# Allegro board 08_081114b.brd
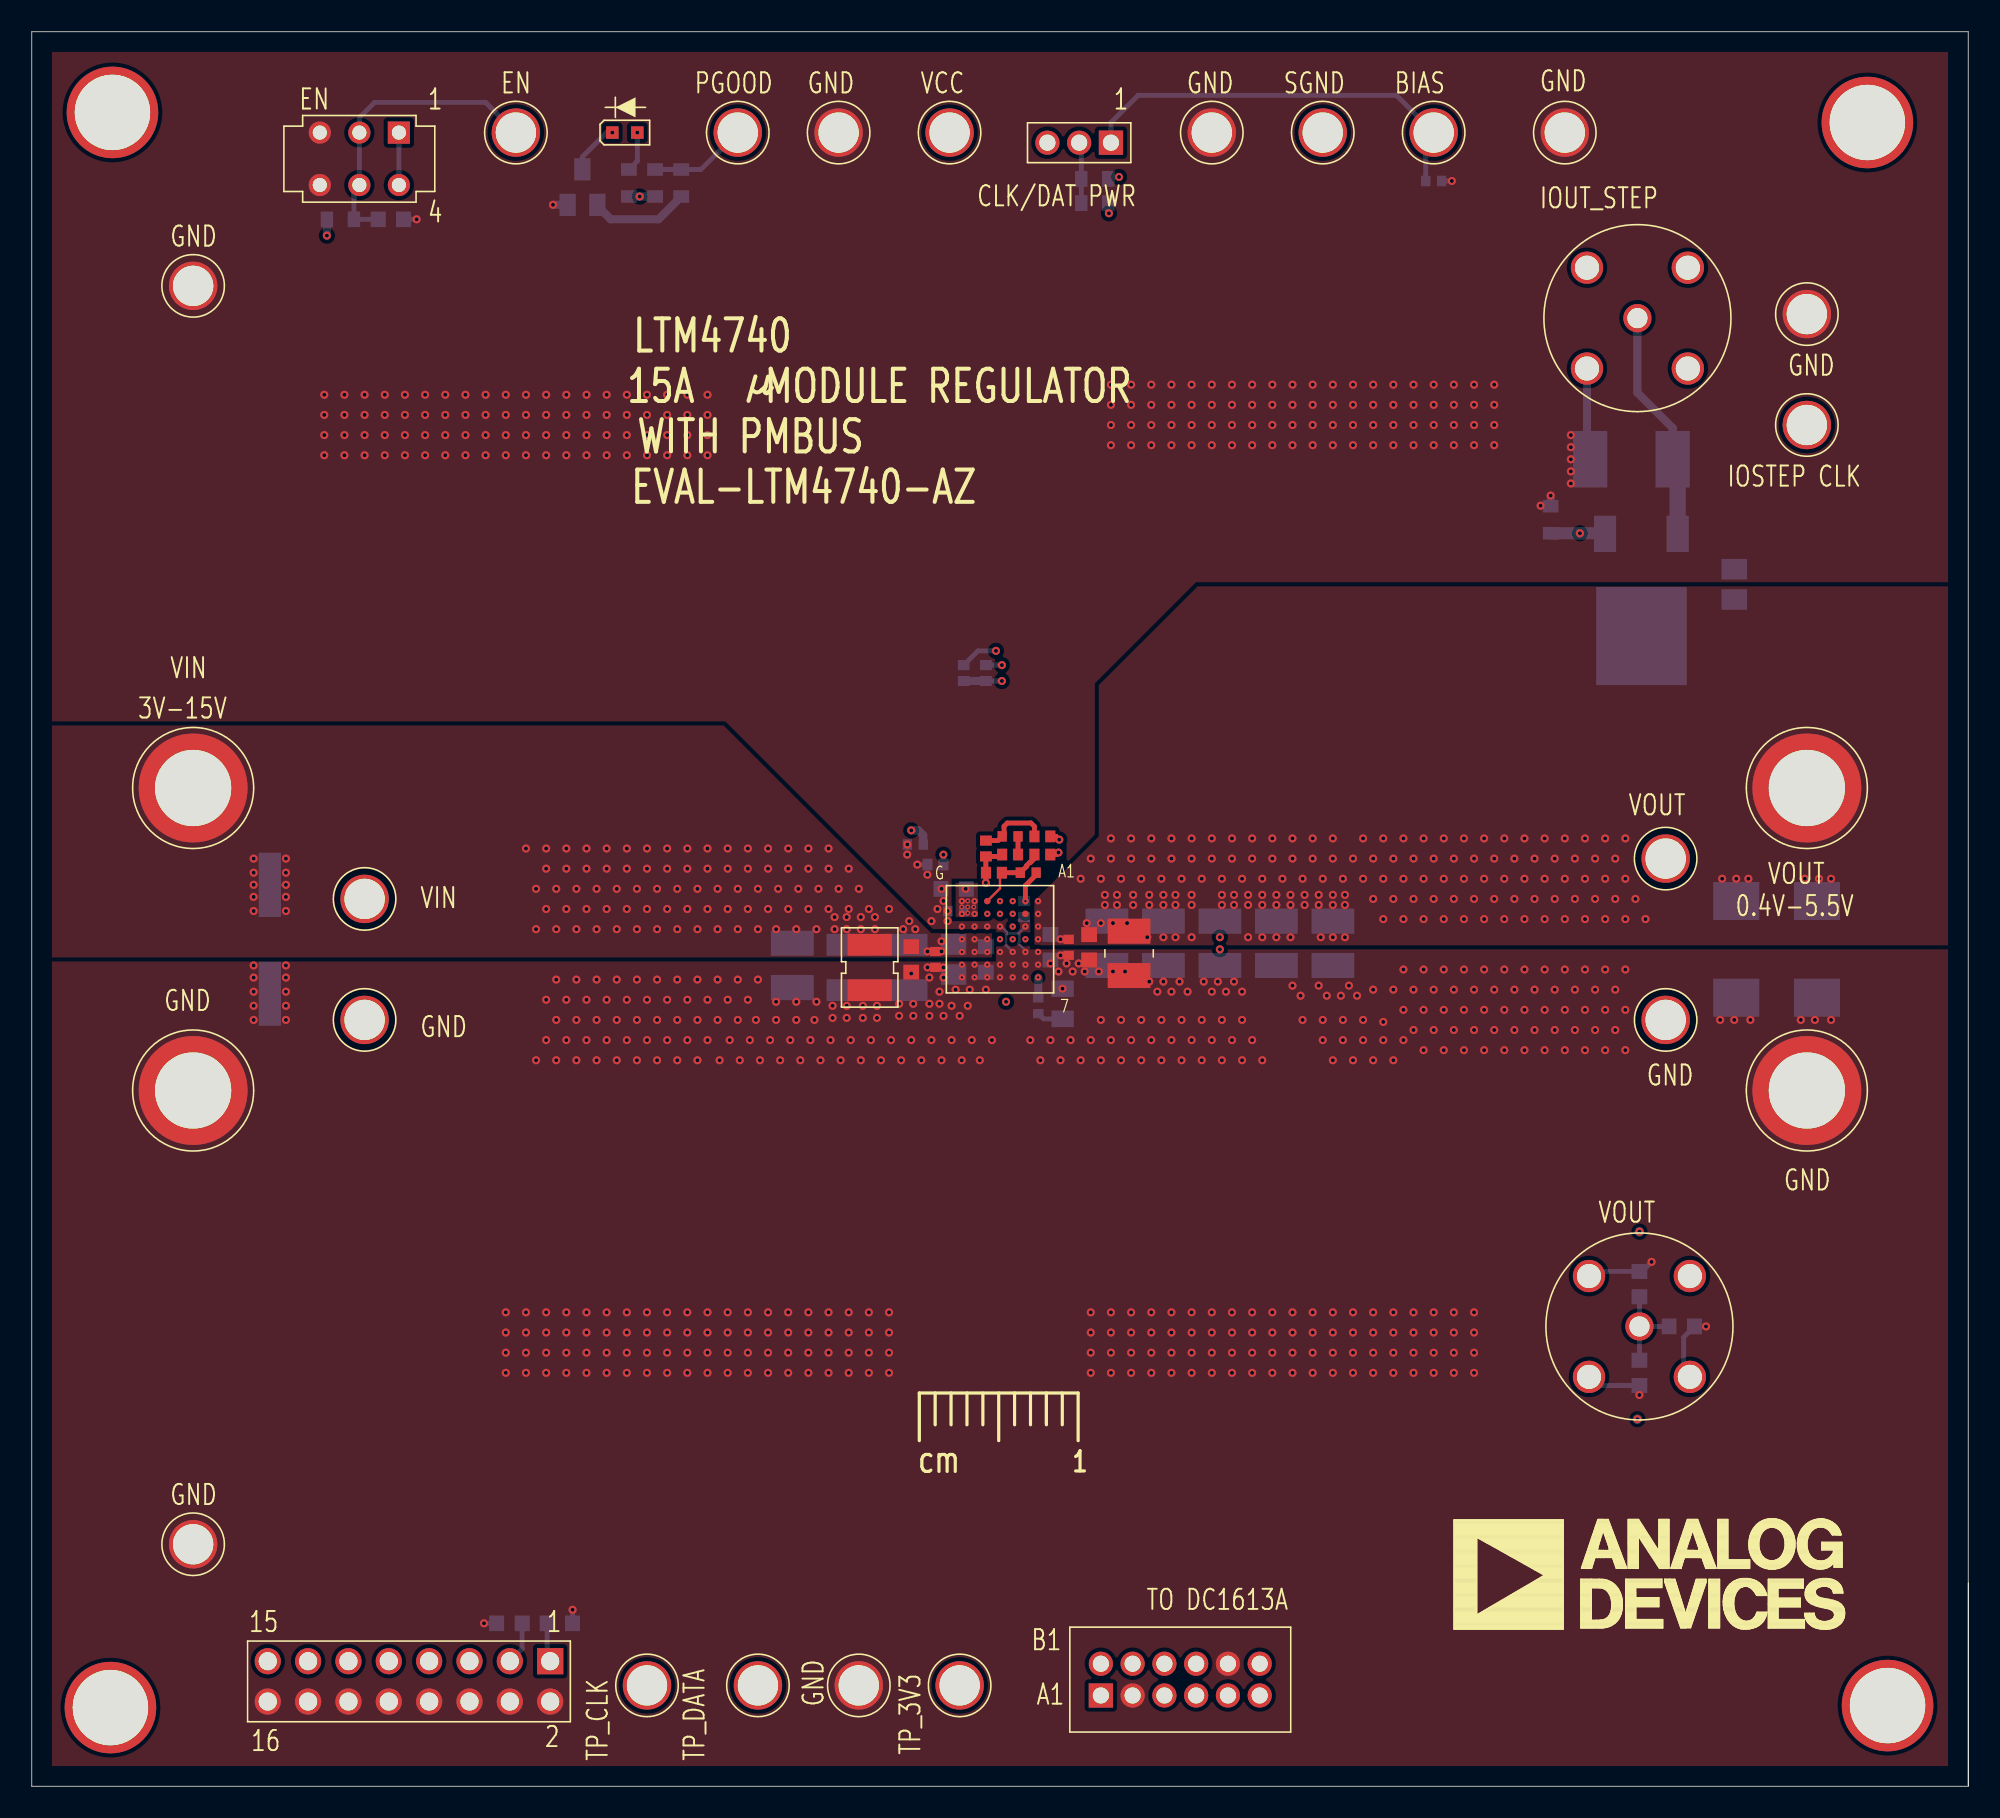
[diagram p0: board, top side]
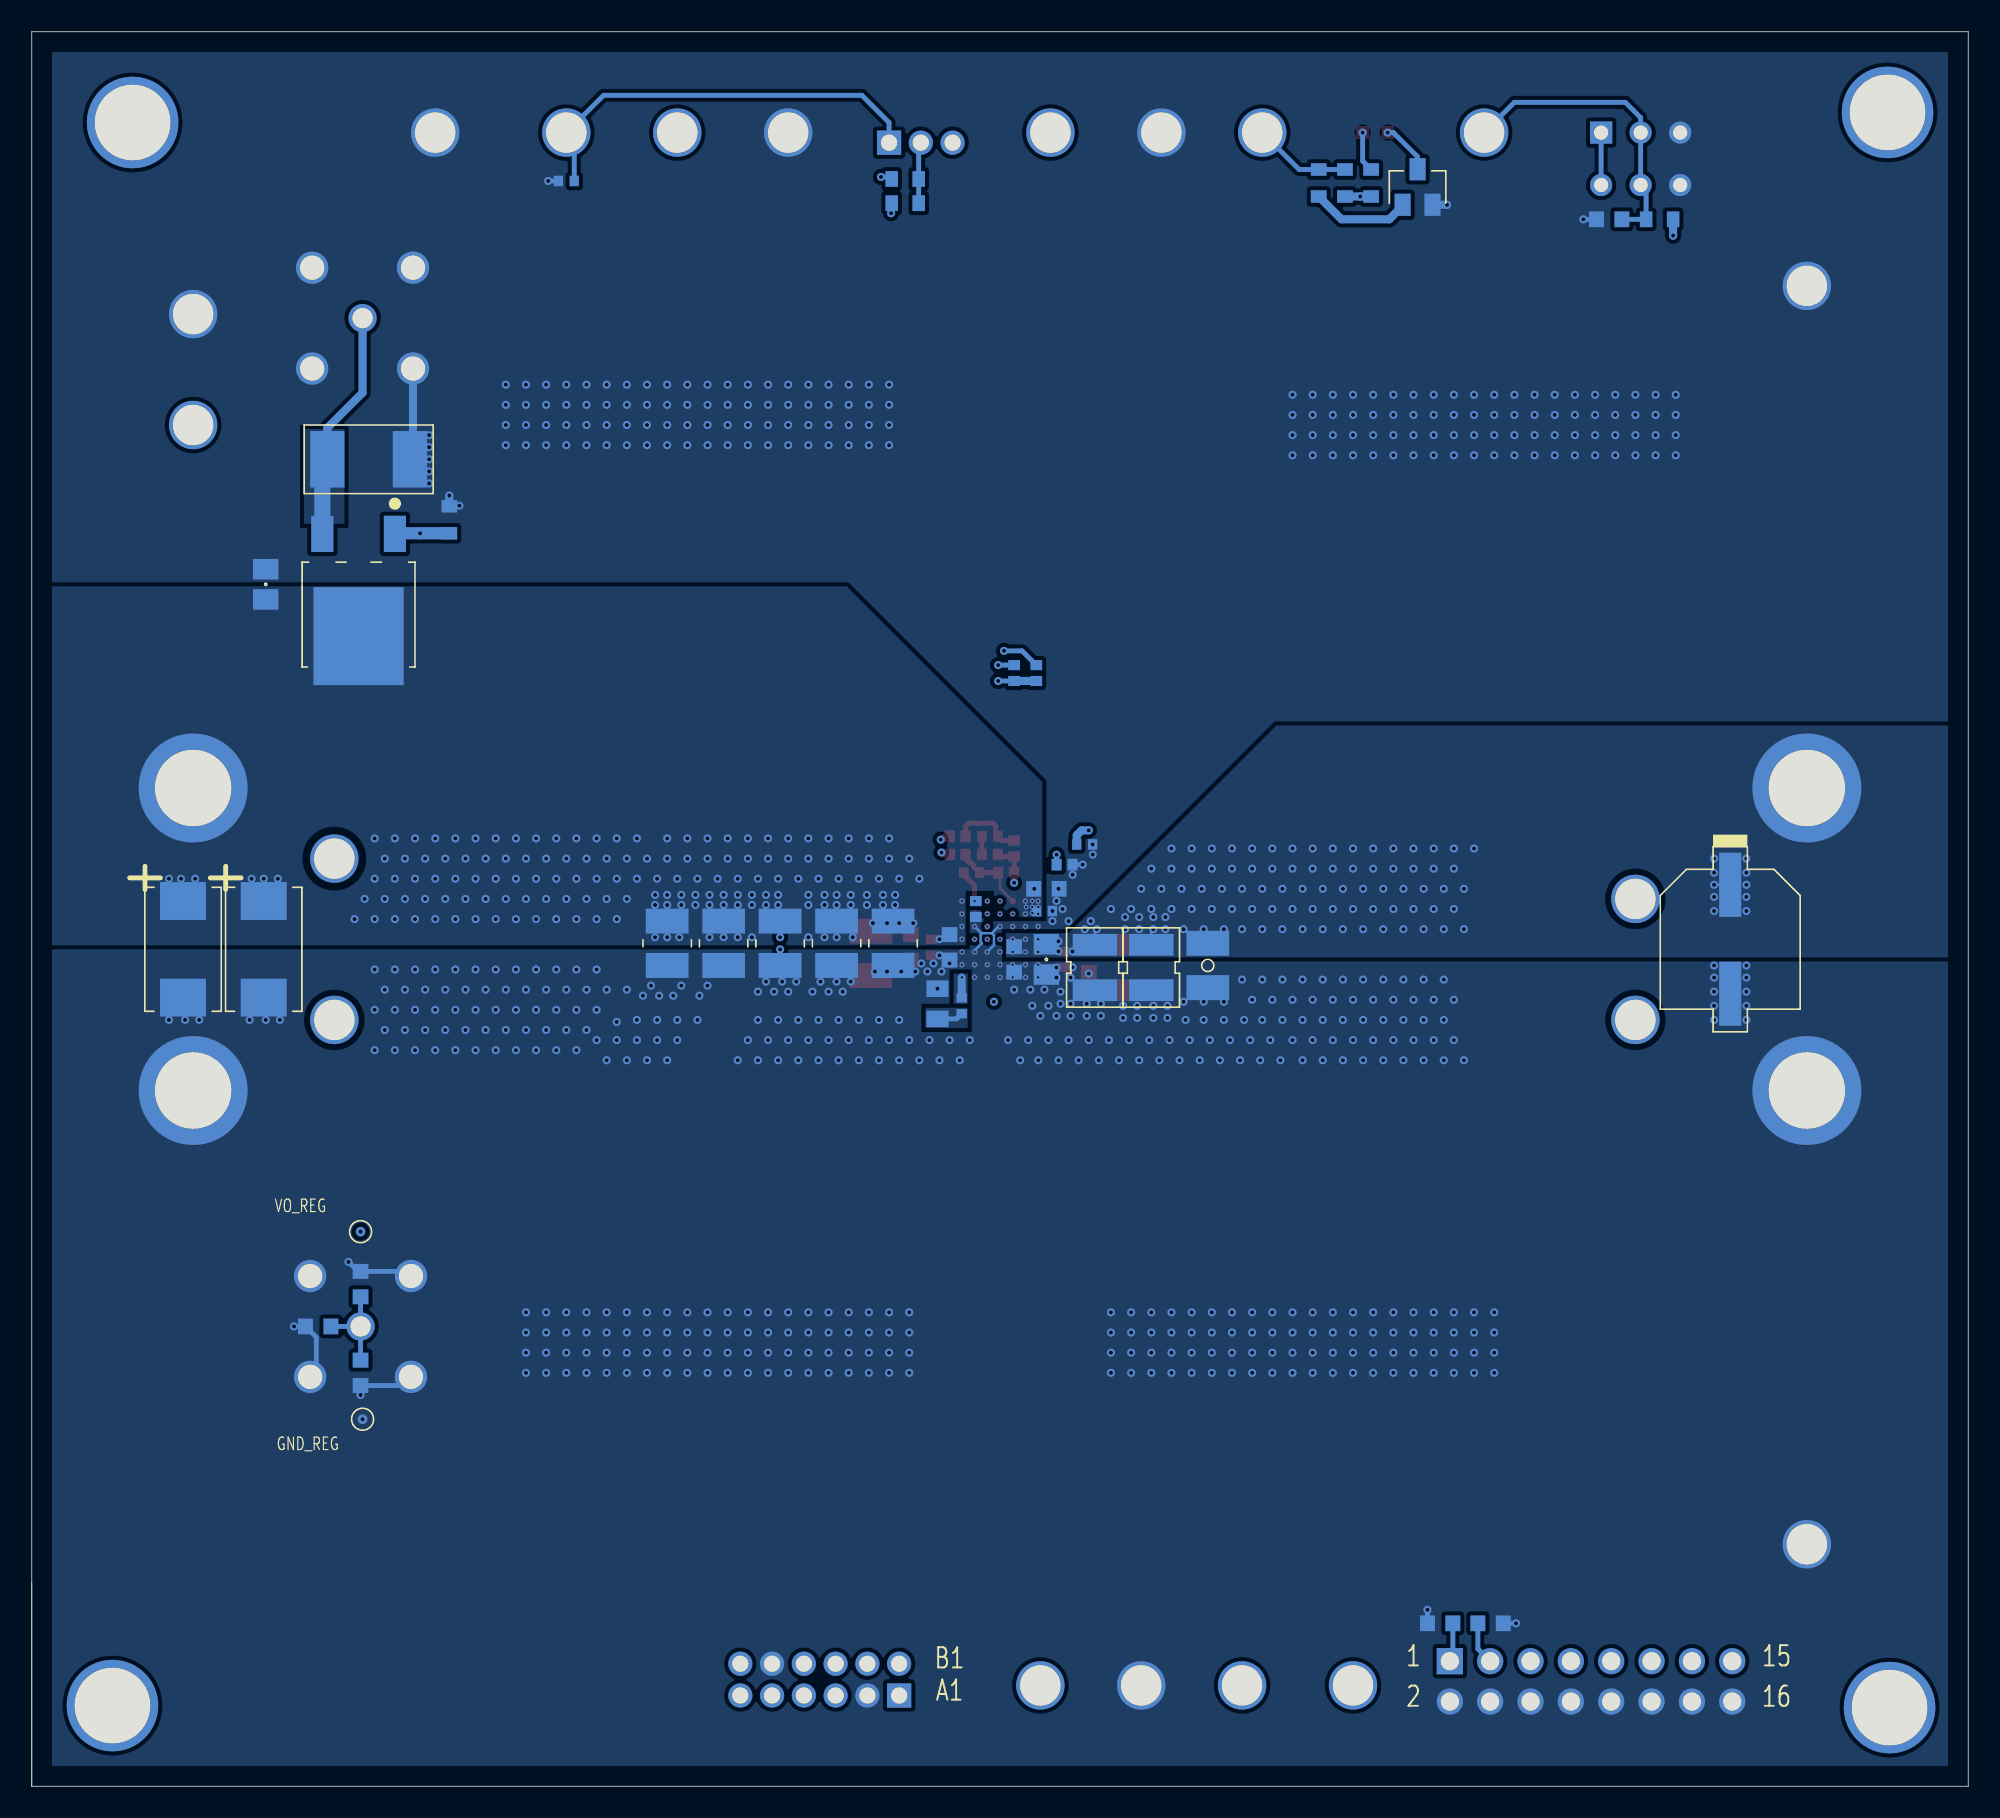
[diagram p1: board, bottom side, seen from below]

Outline 121.92 x 110.49 mm; copper layers: TOP, LAYER_2, LAYER_3, LAYER_4, LAYER_5, BOTTOM. Coordinates in mm from the lower left corner of the outline.
Outline path: 121.92,0 121.92,110.49 0,110.49 0,0 121.92,0 ; 121.92,0 121.92,12.83

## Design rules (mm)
constraint set DEFAULT: min track width 0.152

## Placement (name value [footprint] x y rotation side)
C1  1uF  [C0402]  65.28 52.83 270 top
C2  220UF  [CPLSML327W327H413]  14.99 53.34 270 bottom
C3  22UF  [C1210H110]  54.99 51.56 270 bottom
C4  22UF  [C1210H110]  51.44 51.56 270 bottom
C5  22UF  [C1210H110]  52.76 51.56 270 top
C6  TBD0402  [C0402]  63.37 49.15 270 bottom
C7  22uF  [C0805H60]  58.04 52.07 270 bottom
C8  2.2uF  [C0402]  88.27 101.09 0 bottom
C9  10uF  [C0603]  55.37 52.07 270 top
C10  1NF  [C0603]  22.61 98.68 180 bottom
C11  TBD0603  [C0603]  30.07 10.26 0 bottom
C12  0.22uF  [C0402]  56.9 52.07 270 top
C13  TBD0402  [C0402]  55.63 59.31 0 bottom
C14  TBD0603  [C0603]  33.25 10.26 180 bottom
C15  TBD0402  [C0402]  62.74 57.53 180 top
C16  TBD0402  [C0402]  61.59 59.82 180 top
C17  TBD1210  [C1210]  47.88 51.69 270 bottom
C18  2.2uF  [C0603]  66.57 52.83 270 top
C19  2.2uF  [C0603]  64.14 52.83 270 bottom
C20  10uF  [C0603]  60.07 52.07 270 bottom
C21  220uF  [C1210-2]  67.69 53.09 270 bottom
C22  220uF  [C1210-2]  69.09 52.45 270 top
C23  1uF  [C0603]  101.22 26.04 90 bottom
C24  220uF  [C1210-2]  81.91 53.09 270 bottom
C25  220uF  [C1210-2]  71.25 53.09 270 bottom
C26  1uF  [C0603]  101.22 31.62 270 bottom
C27  220uF  [C1210-2]  78.36 53.09 270 bottom
C28  1uF  [C0805H60]  107.19 75.69 90 bottom
C29  220uF  [C1210-2]  74.8 53.09 270 bottom
C30  1uF  [C0402]  58.17 55.12 180 bottom
C31  330uF  [CPLSML287W169H157]  112.4 52.71 270 bottom
C32  330uF  [CPLSML287W169H157]  107.31 52.71 270 bottom
C33  1uF  [C0603]  58.04 56.52 180 bottom
C34  1uF  [C0603]  103.89 28.96 180 bottom
J1  112404  [CNAMPHENOL112404]  101.09 92.46 0 top
J2  112404  [CNAMPHENOL112404]  101.22 28.96 0 top
NOREF  -  []  23.75 131.7 0 top
NOREF#2  -  []  77.47 146.05 0 top
NOREF#3  -  []  -223.52 -149.22 0 top
NOREF#4  -  []  89.53 3.81 0 top
NOREF#5  -  []  74.3 130.81 0 top
NOREF#6  -  []  122.56 111.12 180 top
NOREF#7  -  []  350.65 266.83 0 top
NOREF#8  -  []  -0.63 -0.63 0 top
NOREF#9  -  []  -223.52 -149.22 0 top
NOREF#10  -  [unnamed#2]  4.95 4.95 0 top
NOREF#11  -  []  0 0 90 top
NOREF#12  -  []  141.29 5.4 0 top
NOREF#13  -  [unnamed#2]  115.57 104.78 0 top
NOREF#14  -  []  -189.92 304.8 0 top
NOREF#15  -  []  -31.12 106.05 0 top
NOREF#16  -  []  157.86 321.18 0 top
NOREF#17  -  []  122.56 -0.63 90 top
NOREF#18  -  []  -0.63 111.12 270 top
NOREF#19  -  []  -31.12 80.01 0 top
NOREF#20  -  []  77.72 -27.94 0 top
NOREF#21  -  [unnamed#2]  116.84 5.08 0 top
NOREF#22  -  []  119.38 152.4 0 top
NOREF#23  -  []  -216.53 130.18 0 top
NOREF#24  -  []  61.47 16.76 0 top
NOREF#25  -  []  23.75 157.73 0 top
NOREF#26  -  [unnamed#2]  5.08 105.41 0 top
NOREF#27  -  []  -223.52 -149.22 0 top
NOREF#28  -  []  347.34 315.6 0 top
NOREF#29  -  []  -193.67 350.52 0 top
NOREF#30  -  []  0 110.49 0 top
NOREF#31  -  []  -189.97 327.66 0 top
P3  98414-G06-12ULF  [CNTHMHDR2X6L528W240H244]  67.31 5.72 0 top
P6  NCTPSMC24_NPM  [TPSMC24_NPM]  101.22 34.93 180 bottom
P10  NRPN031PAEN-RC  [CNTHMHDR1X3L326W79H235]  67.95 103.5 180 top
P11  TSW-108-07-G-D  [CNSAMTECTSW-108-08-G-D-ST]  32.64 7.87 180 top
P12  NCTPSMC24_NPM  [TPSMC24_NPM]  101.09 23.11 180 bottom
PG  LG L29K-G2J1-24-Z  [LED0603-2]  37.34 104.14 0 top
Q1  SUD50N04-8M8P-4GE3  [TO252-3]  101.35 74.68 0 bottom
Q2  BSS138TA  [SOT23]  34.67 100.71 180 bottom
R1  0  [R0402]  63.63 58.67 0 top
R2  TBD0805  [R0805]  64.9 49.28 90 bottom
R3  0  [R0402]  62.48 55.25 90 bottom
R4  TBD0402  [R0402]  56.9 58.04 180 bottom
R6  200  [R0402]  58.67 70.1 90 bottom
R9  309  [R0402]  60.07 70.1 90 bottom
R10  TBD0402  [R0402]  61.59 58.67 0 top
R12  3.01K  [R0402]  60.07 59.06 270 top
R13  3.01K  [R0402]  60.58 57.53 0 top
R16  10  [R0402]  63.63 59.82 0 top
R17  10K  [R0603]  95.63 79.76 270 bottom
R20  0.005  [R2512H31]  100.71 83.57 180 bottom
R21  3.3K  [R0603]  66.93 101.22 0 bottom
R22  3.3K  [R0603]  66.93 99.69 0 bottom
R23  20K  [R0603]  19.43 98.68 0 bottom
R25  20K  [R0603]  39.24 100.97 90 bottom
R26  100  [R0603]  40.89 100.97 270 bottom
R27  210  [R0603]  37.59 100.97 90 bottom
S1  JS202011CQN  [SWTHL354W142H217]  23.11 104.14 180 top
TP1  2501-2-00-80-00-00-07-0  [CNMILLMAX2501]  96.52 104.14 0 top
TP2  2501-2-00-80-00-00-07-0  [CNMILLMAX2501]  57.79 104.14 0 top
TP3  2501-2-00-80-00-00-07-0  [CNMILLMAX2501]  111.76 92.71 0 top
TP4  2501-2-00-80-00-00-07-0  [CNMILLMAX2501]  88.27 104.14 0 top
TP5  2501-2-00-80-00-00-07-0  [CNMILLMAX2501]  20.95 55.88 0 top
TP6  CKFH1032-10  [CNCFCKFH1032-10]  10.16 62.87 0 top
TP7  CKFH1032-10  [CNCFCKFH1032-10]  10.16 43.82 0 top
TP8  2501-2-00-80-00-00-07-0  [CNMILLMAX2501]  20.95 48.26 0 top
TP9  2501-2-00-80-00-00-07-0  [CNMILLMAX2501]  10.16 15.24 0 top
TP10  2501-2-00-80-00-00-07-0  [CNMILLMAX2501]  74.3 104.14 0 top
TP11  2501-2-00-80-00-00-07-0  [CNMILLMAX2501]  10.16 94.49 0 top
TP12  CKFH1032-10  [CNCFCKFH1032-10]  111.76 62.87 0 top
TP13  CKFH1032-10  [CNCFCKFH1032-10]  111.76 43.82 0 top
TP14  2501-2-00-80-00-00-07-0  [CNMILLMAX2501]  30.48 104.14 90 top
TP15  2501-2-00-80-00-00-07-0  [CNMILLMAX2501]  38.73 6.35 0 top
TP16  2501-2-00-80-00-00-07-0  [CNMILLMAX2501]  45.72 6.35 0 top
TP17  2501-2-00-80-00-00-07-0  [CNMILLMAX2501]  44.45 104.14 90 top
TP18  2501-2-00-80-00-00-07-0  [CNMILLMAX2501]  58.42 6.35 0 top
TP19  2501-2-00-80-00-00-07-0  [CNMILLMAX2501]  102.87 58.42 0 top
TP20  2501-2-00-80-00-00-07-0  [CNMILLMAX2501]  102.87 48.26 0 top
TP21  2501-2-00-80-00-00-07-0  [CNMILLMAX2501]  111.76 85.72 0 top
TP22  2501-2-00-80-00-00-07-0  [CNMILLMAX2501]  81.28 104.14 0 top
TP23  2501-2-00-80-00-00-07-0  [CNMILLMAX2501]  50.8 104.14 0 top
TP24  2501-2-00-80-00-00-07-0  [CNMILLMAX2501]  52.07 6.35 0 top
U1  LTM4740EY#PBF  [BGA49_6_25X6_25_H5_39_SMD]  60.96 53.34 180 top

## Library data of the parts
C1 C30 = CAP: User Part Number: UPN; Tolerance: 10; alternate symbols: (C0402); part number: CAP_SM-1UF,10V,10,E017585,C0402; tolerance: 10
C2 = CAPP: Tolerance: 20; User Part Number: UPN; alternate symbols: (CPLSML327W327H413); part number: CAPP_SM-220UF,25V,20,E064730,CPLSML327W327H413; tolerance: 20
C3-C5 = CAP: Tolerance: 10; User Part Number: UPN; alternate symbols: (C1210H110); part number: CAP_SM-22UF,25V,10,E063473,C1210H110; tolerance: 10
C6 C13 C15 C16 = CAP: User Part Number: UPN; alternate symbols: (C0402); part number: CAP_SM-TBD0402,TBD0402,TBD0402,E000381,C0402
C7 = CAP: Tolerance: 20; User Part Number: UPN; alternate symbols: (C0805H60); part number: CAP_SM-22UF,25V,20,E032575,C0805H60; tolerance: 20
C8 = CAP: User Part Number: UPN; Tolerance: 20; alternate symbols: (C0402); part number: CAP_SM-2.2UF,6.3V,20,E007139,C0402; tolerance: 20
C9 C20 = CAP: User Part Number: UPN; Tolerance: 20; alternate symbols: (C0603); part number: CAP_SM-10UF,25V,20,E023693,C0603; tolerance: 20
C10 = CAP: User Part Number: UPN; Tolerance: 10; alternate symbols: (C0603); part number: CAP_SM-1NF,100V,10,E042847,C0603; tolerance: 10
C11 C14 = CAP: User Part Number: UPN; alternate symbols: (C0603); part number: CAP_SM-TBD0603,TBD0603,TBD0603,E000382,C0603
C12 = CAP: User Part Number: UPN; Tolerance: 10; alternate symbols: (C0402); part number: CAP_SM-0.22UF,25V,10,E034257,C0402; tolerance: 10
C17 = CAP: User Part Number: UPN; alternate symbols: (C1210); part number: CAP_SM-TBD1210,TBD1210,TBD1210,E016202,C1210
C18 C19 = CAP: User Part Number: UPN; Tolerance: 10; alternate symbols: (C0603); part number: CAP_SM-2.2UF,10V,10,E015288,C0603; tolerance: 10
C21 C22 C24 C25 C27 C29 = CAP: Tolerance: 20; User Part Number: UPN; alternate symbols: (C1210-2); part number: CAP_SM-220UF,6.3V,20,E031200,C1210-2; tolerance: 20
C23 C26 C33 C34 = CAP: User Part Number: UPN; Tolerance: 10; alternate symbols: (C0603); part number: CAP_SM-1UF,25V,10,E026591,C0603; tolerance: 10
C28 = CAP: Tolerance: 10; User Part Number: UPN; alternate symbols: (C0805H60); part number: CAP_SM-1UF,25V,10,E007664,C0805H60; tolerance: 10
C31 C32 = CAPP: Tolerance: 20; User Part Number: UPN; alternate symbols: (CPLSML287W169H157); part number: CAPP_SM-330UF,10V,20,E013491,CPLSML287W169H157; tolerance: 20
J1 J2 = CNBNC5P: Tolerance: N/A; User Part Number: UPN; alternate symbols: (CNAMPHENOL112404); part number: CNBNC5P_TH-112404,E020078,CNAMPHENOL112404; tolerance: N/A
P3 = CN12P_AB_V2: Tolerance: N/A; User Part Number: UPN; alternate symbols: (CNTHMHDR2X6L528W240H244); part number: CN12P_AB_V2_TH-98414-G06-12ULF,E032251,CNTHMHDR2X6L528W240H244; tolerance: N/A
P6 P12 = NC1P: Tolerance: N/A; User Part Number: UPN; alternate symbols: (TPSMC24_NPM); part number: NC1P_SM-NCTPSMC24_NPM,E056623,TPSMC24_NPM; tolerance: N/A
P10 = CN3P: Tolerance: N/A; User Part Number: UPN; alternate symbols: (CNTHMHDR1X3L326W79H235); part number: CN3P_TH-NRPN031PAEN-RC,E048452,CNTHMHDR1X3L326W79H235; tolerance: N/A
P11 = CN16P_ODD_EVEN: Tolerance: N/A; User Part Number: UPN; alternate symbols: (CNSAMTECTSW-108-08-G-D-ST); part number: CN16P_ODD_EVEN_TH-TSW-108-07-G-D,E007878,CNSAMTECTSW-108-08-G-D-ST; tolerance: N/A
PG = DIOLED: Tolerance: N/A; User Part Number: UPN; alternate symbols: (LED0603-2); part number: DIOLED_SM-LG L29K-G2J1-24-Z,N/A,N/A,E010948,LED0603-2; tolerance: N/A
Q1 = TRANNMOSFET_V8: Tolerance: N/A; User Part Number: UPN; alternate symbols: (TO252-3); part number: TRANNMOSFET_V8_SM-SUD50N04-8M8P-4GE3,E027839,TO252-3; tolerance: N/A
Q2 = TRANBSS138: User Part Number: UPN; Tolerance: N/A; alternate symbols: (SOT23); part number: TRANBSS138_SM-BSS138-7-F,E004635,SOT23; tolerance: N/A
R1 R3 = RES: User Part Number: UPN; Tolerance: JUMPER; alternate symbols: (R0402); part number: RES_SM-0,E003438,1/10W,JUMPER,R0402; tolerance: JUMPER
R2 = RES: User Part Number: UPN; alternate symbols: (R0805); part number: RES_SM-TBD0805,E004051,TBD0805,TBD0805,R0805
R4 R10 = RES: User Part Number: UPN; alternate symbols: (R0402); part number: RES_SM-TBD0402,E004049,TBD0402,TBD0402,R0402
R6 = RES: User Part Number: UPN; Tolerance: 1; alternate symbols: (R0402); part number: RES_SM-200,E003753,1/10W,1,R0402; tolerance: 1
R9 = RES: User Part Number: UPN; Tolerance: 1; alternate symbols: (R0402); part number: RES_SM-309,E006547,1/10W,1,R0402; tolerance: 1
R12 R13 = RES: User Part Number: UPN; Tolerance: 1; alternate symbols: (R0402); part number: RES_SM-3.01K,E027299,1/10W,1,R0402; tolerance: 1
R16 = RES: User Part Number: UPN; Tolerance: 1; alternate symbols: (R0402); part number: RES_SM-10,E003768,1/10W,1,R0402; tolerance: 1
R17 = RES: User Part Number: UPN; Tolerance: 1; alternate symbols: (R0603); part number: RES_SM-10K,E003671,1/10W,1,R0603; tolerance: 1
R20 = RES: User Part Number: UPN; Tolerance: 1; alternate symbols: (R2512H31); part number: RES_SM-0.005,E035239,1W,1,R2512H31; tolerance: 1
R21 R22 = RES: User Part Number: UPN; Tolerance: 5; alternate symbols: (R0603); part number: RES_SM-3.3K,E036086,1/4W,5,R0603; tolerance: 5
R23 = RES: User Part Number: UPN; Tolerance: 5; alternate symbols: (R0603); part number: RES_SM-20K,E003851,1/10W,5,R0603; tolerance: 5
R25 = RES: User Part Number: UPN; Tolerance: 5; alternate symbols: (R0603); part number: RES_SM-20K,E060185,1/10W,5,R0603; tolerance: 5
R26 = RES: User Part Number: UPN; Tolerance: 1; alternate symbols: (R0603); part number: RES_SM-100,E003668,1/10W,1,R0603; tolerance: 1
R27 = RES: User Part Number: UPN; Tolerance: 1; alternate symbols: (R0603); part number: RES_SM-210,E042869,1/10W,1,R0603; tolerance: 1
S1 = SWDPDT_V5: Tolerance: N/A; User Part Number: UPN; alternate symbols: (SWTHL354W142H217); part number: SWDPDT_V5_TH-JS202011CQN,E025828,SWTHL354W142H217; tolerance: N/A
TP1-TP5 TP8-TP11 TP14-TP24 = CNTP1P: User Part Number: UPN; Tolerance: N/A; alternate symbols: (CNMILLMAX2501); part number: CNTP1P_TH-2501-2-00-80-00-00-07-0,E031108,CNMILLMAX2501; tolerance: N/A
TP6 TP7 TP12 TP13 = CNTP1P: Tolerance: N/A; User Part Number: UPN; alternate symbols: (CNCFCKFH1032-10); part number: CNTP1P_TH-CKFH1032-10,E050511,CNCFCKFH1032-10; tolerance: N/A
U1 = ADLTM4740: Tolerance: N/A; User Part Number: UPN; alternate symbols: (BGA49_6_25X6_25_H5_39_SMD); part number: ADLTM4740_SM-LTM4740EY#PBF,E064685,BGA49_6_25X6_25_H5_39_SMD; tolerance: N/A

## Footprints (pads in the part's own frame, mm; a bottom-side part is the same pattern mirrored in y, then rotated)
BGA49_6_25X6_25_H5_39_SMD
  round 0.406 smd: A1(-2.4,-2.4) A2(-2.4,-1.6) A3(-2.4,-0.8) A4(-2.4,0) A5(-2.4,0.8) A6(-2.4,1.6) A7(-2.4,2.4) B1(-1.6,-2.4) B2(-1.6,-1.6) B3(-1.6,-0.8) B4(-1.6,0) B5(-1.6,0.8) B6(-1.6,1.6) B7(-1.6,2.4) C1(-0.8,-2.4) C2(-0.8,-1.6) C3(-0.8,-0.8) C4(-0.8,0) C5(-0.8,0.8) C6(-0.8,1.6) C7(-0.8,2.4) D1(0,-2.4) D2(0,-1.6) D3(0,-0.8) D4(0,0) D5(0,0.8) D6(0,1.6) D7(0,2.4) E1(0.8,-2.4) E2(0.8,-1.6) E3(0.8,-0.8) E4(0.8,0) E5(0.8,0.8) E6(0.8,1.6) E7(0.8,2.4) F1(1.6,-2.4) F2(1.6,-1.6) F3(1.6,-0.8) F4(1.6,0) F5(1.6,0.8) F6(1.6,1.6) F7(1.6,2.4) G1(2.4,-2.4) G2(2.4,-1.6) G3(2.4,-0.8) G4(2.4,0) G5(2.4,0.8) G6(2.4,1.6) G7(2.4,2.4)
C0402
  rect 0.584x0.66 smd: 1(-0.5,0) 2(0.5,0)
C0603
  rect 0.94x0.991 smd: 1(-0.8,0) 2(0.8,0)
C0805H60
  rect 1.295x1.6 smd: 1(-0.953,0) 2(0.953,0)
C1210
  rect 1.575x2.692 smd: 1(-1.397,0) 2(1.397,0)
C1210-2
  rect 1.575x2.692 smd: 1(-1.397,0) 2(1.397,0)
C1210H110
  rect 1.372x2.794 smd: 1(-1.431,0) 2(1.431,0)
CNAMPHENOL112404
  round 1.778 hole 1.27: 1(0,0)
  round 2.032 hole 1.524: 2(-3.175,3.175) 3(3.175,3.175) 4(3.175,-3.175) 5(-3.175,-3.175)
CNCFCKFH1032-10
  round 6.858 hole 4.801: 1(0,0)
CNMILLMAX2501
  round 3.048 hole 2.54: 1(0,0)
CNSAMTECTSW-108-08-G-D-ST
  rect 1.651x1.651 hole 1.143: 1(0,0)
  round 1.651 hole 1.143: 2(0,2.54) 3(2.54,0) 4(2.54,2.54) 5(5.08,0) 6(5.08,2.54) 7(7.62,0) 8(7.62,2.54) 9(10.16,0) 10(10.16,2.54) 11(12.7,0) 12(12.7,2.54) 13(15.24,0) 14(15.24,2.54) 15(17.78,0) 16(17.78,2.54)
CNTHMHDR1X3L326W79H235
  rect 1.524x1.524 hole 1.016: 1(0,0)
  round 1.524 hole 1.016: 2(2,0) 3(4,0)
CNTHMHDR2X6L528W240H244
  rect 1.524x1.524 hole 1.016: A1(0,0)
  round 1.524 hole 1.016: A2(2,0) A3(4,0) A4(6,0) A5(8,0) A6(10,0) B1(0,2) B2(2,2) B3(4,2) B4(6,2) B5(8,2) B6(10,2)
CPLSML287W169H157
  rect 2.388x2.896 smd: N(3.044,0) P(-3.044,0)
CPLSML327W327H413
  rect 4.039x1.397 smd: N(3.43,0) P(-3.43,0)
LED0603-2
  rect 0.787x0.787 smd: A(0.787,0) C(-0.787,0)
R0402
  rect 0.635x0.737 smd: 1(-0.5,0) 2(0.5,0)
R0603
  rect 0.787x0.991 smd: 1(-0.85,0) 2(0.85,0)
R0805
  rect 1.041x1.397 smd: 1(-0.95,0) 2(0.95,0)
R2512H31
  rect 2.159x3.556 smd: 1(-2.6,0) 2(2.6,0)
SOT23
  rect 1.016x1.397 smd: 1(-0.94,-1.118) 2(0.94,-1.118) 3(0,1.118)
SWTHL354W142H217
  rect 1.397x1.397 hole 0.889: 1(0,0)
  round 1.397 hole 0.889: 2(2.489,0) 3(4.978,0) 4(0,3.302) 5(2.489,3.302) 6(4.978,3.302)
TO252-3
  rect 1.397x2.286 smd: 1(-2.29,-4.191) 2(2.28,-4.191)
  rect 5.69x6.172 smd: 3(0,2.248)
TPSMC24_NPM
  round 0.61 smd: 1(0,0)
unnamed#2
  round 5.766 hole 4.75 unplated: (0,0)

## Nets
3V3: P3.A3 TP18.1(N1)
AVDD: U1.B2
GND_POWER: C1.2(N2) C2.N(N2) C3.2(N2) C4.2(N2) C5.2(N2) C7.2(N2) C8.2(N2) C9.2(N2) C10.1 C11.1 C12.2(N2) C13.1 C14.1 C17.2(N2) C18.2(N2) C19.2(N2) C20.2(N2) C21.2(N2) C22.2(N2) C23.1 C24.2(N2) C25.2(N2) C26.1 C27.2(N2) C28.2(N2) C29.2(N2) C30.2(N2) C31.N(N2) C32.N(N2) C33.2(N2) C34.1 J1.2 J1.3 J1.4 J1.5(SH4) J2.2 J2.3 J2.4 J2.5(SH4) P3.A2 P3.B5 P11.2 P11.4 P11.6 P11.8 P11.10 P11.12 P11.14 P11.16(N8) P12.1(N1) Q2.2(S) R1.2(N2) R2.2(N2) R3.1 R4.2(N2) R17.1 R20.2(N2) S1.3 S1.6(NO2) TP1.1(N1) TP3.1(N1) TP7.1(N1) TP8.1(N1) TP9.1(N1) TP10.1(N1) TP11.1(N1) TP13.1(N1) TP20.1(N1) TP23.1(N1) TP24.1(N1) U1.A5 U1.A6 U1.B3 U1.B5 U1.B6 U1.B7 U1.C5 U1.C6 U1.C7 U1.D3 U1.D5 U1.D6 U1.D7 U1.E3 U1.E6 U1.E7 U1.F3 U1.F6 U1.F7 U1.G3 U1.G6 U1.G7
GND_SIGNAL: C15.1 R3.2(N2) R4.1 R6.1 R9.1 TP22.1(N1) U1.B1
VCC: C13.2(N2) P10.3(N3) R23.1 R25.1 R27.1 TP2.1(N1) U1.C2
VIN: C2.P C3.1 C4.1 C5.1 C7.1 C9.1 C12.1 C17.1 C20.1 TP5.1(N1) TP6.1(N1) U1.E4 U1.E5 U1.F4 U1.F5 U1.G4 U1.G5
BIAS: C8.1 P10.1 TP4.1(N1) U1.B4
CLK: C14.2(N2) P3.B2 P11.1 R21.2(N2) TP15.1(N1) U1.D2
DATA: C11.2(N2) P3.B1 P11.3 R22.2(N2) TP16.1(N1) U1.D1
EN: C10.2(N2) R23.2(N2) S1.2 S1.5 TP14.1(N1) U1.C4
PGOOD: R25.2(N2) R26.1 TP17.1(N1) U1.D4
UNNAMED_2_ADLTM4740_I1_PGM0: R6.2(N2) U1.C1
UNNAMED_2_ADLTM4740_I1_PGM1: R9.2(N2) U1.C3
UNNAMED_2_ADLTM4740_I1_SNSN: C15.2(N2) R1.1 R13.2(N2) U1.E1
UNNAMED_2_ADLTM4740_I1_SNSP: R10.1 R12.2(N2) R13.1 U1.E2
UNNAMED_2_ADLTM4740_I1_SW: C6.1 U1.A7
UNNAMED_2_CAP_I18_N1: C16.1 R10.2(N2)
UNNAMED_2_CAP_I18_N2: C16.2(N2) R12.1 R16.1
UNNAMED_2_CAP_I228_N2: C6.2(N2) R2.1
UNNAMED_2_CNBNC5P_I173_CNTR: J1.1 Q1.2(S) R20.1
UNNAMED_2_CNTP1P_I182_N1: Q1.1 R17.2(N2) TP21.1(N1)
UNNAMED_6_CN3P_I255_N2: P10.2 R21.1 R22.1
UNNAMED_6_DIOLED_I288_N: PG.C Q2.3
UNNAMED_6_DIOLED_I288_P: PG.A(P) R27.2(N2)
UNNAMED_6_RES_I285_N2: Q2.1 R26.2(N2)
UNNAMED_6_SWDPDTV5_I246_NC1: S1.1 S1.4
VOUT: C1.1 C18.1 C19.1 C21.1 C22.1 C23.2(N2) C24.1 C25.1 C26.2(N2) C27.1 C28.1 C29.1 C30.1 C31.P C32.P C33.1 C34.2(N2) J2.1 P6.1(N1) Q1.3 R16.2(N2) TP12.1(N1) TP19.1(N1) U1.A1 U1.A2 U1.A3 U1.A4 U1.F1 U1.F2 U1.G1 U1.G2(VOUT_8)

Pads without a net: P3 A1 A4 A5 A6 B3 B4 B6; P11 5 7 9 11 13 15

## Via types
v1: diameter 0.305, hole 0.152, TOP to BOTTOM, 52 vias
v2: diameter 0.508, hole 0.254, TOP to BOTTOM, 901 vias

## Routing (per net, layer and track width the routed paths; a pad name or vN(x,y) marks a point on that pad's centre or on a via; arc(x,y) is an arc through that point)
3V3: length 14.8
  LAYER_4 w0.305: TP18.1 59.77,6.35 62.33,3.78 69.38,3.78 P3.A3
GND_POWER: length 217.5
  TOP w0.305: v2(64.64,58.8) 64.52,58.67 R1.2
  LAYER_2 w0.152: 61.34,53.85 61.47,53.72 62.14,53.72 ; 61.34,53.85 61.05,54.14 61,54.14 ; 61.34,53.85 61.34,53.09 60.96,52.71 60.96,52.58 ; 62.48,54.1 62.48,54.06 62.14,53.72 ; 62.48,54.1 62.48,54.22 62.14,54.56 61.42,54.56 61,54.14 ; 62.48,54.1 62.6,54.1 62.99,53.71 62.98,53.7 62.98,53.1 63.36,52.72 v1(63.36,52.54) ; 62.48,54.1 62.56,54.18 ; 62.14,53.72 62.14,53.5 62.14,53.5 62.14,53.18 62.14,53.18 62.14,52.96 v1(62.56,52.54) ; 60.96,52.58 60.58,52.96 60.58,53.76 v1(60.96,54.14) 61,54.14 ; 60.96,52.58 v1(60.96,52.54)
  LAYER_3 w0.305: v2(101.09,23.11) 98.43,25.78 J2.5 98.04,27.31 77.85,47.5 77.85,50.29 75.44,52.71 v2(74.8,52.71)
  LAYER_4 w0.305: TP20.1 103,48.39 103,52.45 102.36,53.09 85.72,53.09 84.07,51.44 69.85,51.44 68.71,52.58 65.02,52.58 v2(64.77,52.32) 64.14,52.96 64.14,58.29 v2(64.64,58.8)
  LAYER_4 w0.508: J2.5 J2.4 J2.3 J2.2 ; 104.27,89.28 104.27,95.63 J1.2 J1.5
  LAYER_5 w0.152: 61.34,53.72 61.34,52.83 61.05,52.54 v1(60.96,52.54) 60.58,52.92 60.58,53.85 60.87,54.14 v1(60.96,54.14) 60.96,54.1 61.34,53.72 ; 61.34,53.72 62.14,53.72 ; 62.14,53.72 62.14,53.72 62.14,52.96 v1(62.56,52.54) 62.57,52.54 62.94,52.91 62.94,53.77 62.61,54.1 62.48,54.1 62.48,54.06 62.14,53.72
  LAYER_5 w0.305: TP8.1 24.51,51.82 56.15,51.82 v2(56.4,51.57)
  BOTTOM w0.152: R20.2 v2(96.9,83.57) ; v1(61.76,52.54) 61.34,52.96 61.34,53.59 61.47,53.72 ; 61.47,53.72 62.14,53.72 ; 61.47,53.72 61.05,54.14 v1(60.96,54.14) ; v1(62.56,52.54) 62.56,52.63 62.1,53.09 62.18,53.16 62.18,53.61 62.1,53.68 62.14,53.72 ; 62.14,53.72 v1(62.56,54.14)
  BOTTOM w0.305: C10.1 v2(24.23,98.68) ; R4.2 v2(55.75,58.04) ; C8.2 v2(89.41,101.09) ; C11.1 v2(28.47,10.26) ; J2.5 98.59,25.23 C23.1 v2(101.22,24.64) ; v2(101.98,33.02) 101.38,32.42 C26.1 98.34,32.42 J2.2 ; C14.1 v2(34.05,11.11) ; J2.4 104.01,26.17 104.01,28.28 C34.1 105.16,28.96 ; C29.2 v2(74.8,52.71)
  BOTTOM w0.508: R20.2 97.92,83.76 J1.5 ; v2(32.82,99.59) Q2.2 ; R17.1 v2(95.63,81.28)
  vias: v1(58.56,54.14) v1(58.56,51.74) v1(58.56,50.94) v1(59.36,54.14) v1(59.36,51.74) v1(59.36,50.94) v1(60.16,54.14) v1(60.16,51.74) v1(60.16,50.94) v1(60.96,51.74) v1(60.96,50.94) v1(61.76,51.74) v1(61.76,50.94) v1(62.56,51.74) v1(62.56,50.94) v1(63.36,51.74) v2(13.97,51.69) v2(13.97,50.93) v2(13.97,50.04) v2(13.97,49.15) v2(13.97,48.26) v2(16,51.69) v2(16,50.93) v2(16,50.04) v2(16,49.15) v2(16,48.26) v2(18.41,87.63) v2(18.41,86.36) v2(18.41,85.09) v2(18.41,83.82) v2(19.69,87.63) v2(19.69,86.36) v2(19.69,85.09) v2(19.69,83.82) v2(20.95,87.63) v2(20.95,86.36) v2(20.95,85.09) v2(20.95,83.82) v2(22.23,87.63) v2(22.23,86.36) v2(22.23,85.09) v2(22.23,83.82) v2(23.49,87.63) v2(23.49,86.36) v2(23.49,85.09) v2(23.49,83.82) v2(24.77,87.63) v2(24.77,86.36) v2(24.77,85.09) v2(24.77,83.82) v2(26.04,87.63) v2(26.04,86.36) v2(26.04,85.09) v2(26.04,83.82) v2(27.3,87.63) v2(27.3,86.36) v2(27.3,85.09) v2(27.3,83.82) v2(28.58,87.63) v2(28.58,86.36) v2(28.58,85.09) v2(28.58,83.82) v2(29.85,87.63) v2(29.85,86.36) v2(29.85,85.09) v2(29.85,83.82) v2(29.85,29.85) v2(29.85,28.58) v2(29.85,27.31) v2(29.85,26.04) v2(31.12,87.63) v2(31.12,86.36) v2(31.12,85.09) v2(31.12,83.82) v2(31.12,29.85) v2(31.12,28.58) v2(31.12,27.31) v2(31.12,26.04) v2(31.75,45.72) v2(32.39,87.63) v2(32.39,86.36) v2(32.39,85.09) v2(32.39,83.82) v2(32.39,49.53) v2(32.39,46.99) v2(32.39,29.85) v2(32.39,28.58) v2(32.39,27.31) v2(32.39,26.04) v2(33.02,50.8) v2(33.02,48.26) v2(33.02,45.72) v2(33.66,87.63) v2(33.66,86.36) v2(33.66,85.09) v2(33.66,83.82) v2(33.66,49.53) v2(33.66,46.99) v2(33.66,29.85) v2(33.66,28.58) v2(33.66,27.31) v2(33.66,26.04) v2(34.29,50.8) v2(34.29,48.26) v2(34.29,45.72) v2(34.92,87.63) v2(34.92,86.36) v2(34.92,85.09) v2(34.92,83.82) v2(34.92,49.53) v2(34.92,46.99) v2(34.92,29.85) v2(34.92,28.58) v2(34.92,27.31) v2(34.92,26.04) v2(35.56,50.8) v2(35.56,48.26) v2(35.56,45.72) v2(36.2,87.63) v2(36.2,86.36) v2(36.2,85.09) v2(36.2,83.82) v2(36.2,49.53) v2(36.2,46.99) v2(36.2,29.85) v2(36.2,28.58) v2(36.2,27.31) v2(36.2,26.04) v2(36.83,50.8) v2(36.83,48.26) v2(36.83,45.72) v2(37.47,87.63) v2(37.47,86.36) v2(37.47,85.09) v2(37.47,83.82) v2(37.47,49.53) v2(37.47,46.99) v2(37.47,29.85) v2(37.47,28.58) v2(37.47,27.31) v2(37.47,26.04) v2(38.1,50.8) v2(38.1,48.26) v2(38.1,45.72) v2(38.73,87.63) v2(38.73,86.36) v2(38.73,85.09) v2(38.73,83.82) v2(38.73,49.53) v2(38.73,46.99) v2(38.73,29.85) v2(38.73,28.58) v2(38.73,27.31) v2(38.73,26.04) v2(39.37,50.8) v2(39.37,48.26) v2(39.37,45.72) v2(40.01,87.63) v2(40.01,86.36) v2(40.01,85.09) v2(40.01,83.82) v2(40.01,49.53) v2(40.01,46.99) v2(40.01,29.85) v2(40.01,28.58) v2(40.01,27.31) v2(40.01,26.04) v2(40.64,50.8) v2(40.64,48.26) v2(40.64,45.72) v2(41.28,87.63) v2(41.28,86.36) v2(41.28,85.09) v2(41.28,83.82) v2(41.28,49.53) v2(41.28,46.99) v2(41.28,29.85) v2(41.28,28.58) v2(41.28,27.31) v2(41.28,26.04) v2(41.91,50.8) v2(41.91,48.26) v2(41.91,45.72) v2(42.55,87.63) v2(42.55,86.36) v2(42.55,85.09) v2(42.55,83.82) v2(42.55,49.53) v2(42.55,46.99) v2(42.55,29.85) v2(42.55,28.58) v2(42.55,27.31) v2(42.55,26.04) v2(43.18,50.8) v2(43.18,48.26) v2(43.31,45.72) v2(43.81,49.53) v2(43.81,29.85) v2(43.81,28.58) v2(43.81,27.31) v2(43.81,26.04) v2(43.94,46.99) v2(44.45,50.8) v2(44.45,48.26) v2(44.58,45.72) v2(45.09,49.53) v2(45.09,29.85) v2(45.09,28.58) v2(45.09,27.31) v2(45.09,26.04) v2(45.21,46.99) v2(45.59,48.26) v2(45.72,50.8) v2(45.85,45.72) v2(46.36,29.85) v2(46.36,28.58) v2(46.36,27.31) v2(46.36,26.04) v2(46.48,46.99) v2(46.86,49.4) v2(46.86,48.26) v2(47.12,45.72) v2(47.62,29.85) v2(47.62,28.58) v2(47.62,27.31) v2(47.62,26.04) v2(47.75,46.99) v2(48.13,49.4) v2(48.13,48.26) v2(48.39,45.72) v2(48.9,29.85) v2(48.9,28.58) v2(48.9,27.31) v2(48.9,26.04) v2(49.02,46.99) v2(49.28,48.26) v2(49.4,49.4) v2(49.66,45.72) v2(50.16,29.85) v2(50.16,28.58) v2(50.16,27.31) v2(50.16,26.04) v2(50.29,46.99) v2(50.42,49.15) v2(50.42,48.39) v2(50.93,45.72) v2(51.31,49.15) v2(51.31,48.39) v2(51.44,29.85) v2(51.44,28.58) v2(51.44,27.31) v2(51.44,26.04) v2(51.56,46.99) v2(52.2,45.72) v2(52.32,49.15) v2(52.32,48.39) v2(52.7,29.85) v2(52.7,28.58) v2(52.7,27.31) v2(52.7,26.04) v2(52.83,46.99) v2(53.21,49.15) v2(53.21,48.39) v2(53.47,45.72) v2(53.98,29.85) v2(53.98,28.58) v2(53.98,27.31) v2(53.98,26.04) v2(54.1,46.99) v2(54.61,49.28) v2(54.61,48.51) v2(54.74,45.72) v2(55.13,59.31) v2(55.12,58.67) v2(55.37,51.18) v2(55.37,46.99) v2(55.5,49.28) v2(55.5,48.51) v2(56.01,45.72) v2(56.39,57.4) v2(56.52,50.93) v2(56.52,49.28) v2(56.52,48.51) v2(56.64,54.48) v2(56.64,46.99) v2(57.02,55.25) v2(57.15,50.04) v2(57.15,49.28) v2(57.28,56.52) v2(57.28,45.72) v2(57.4,55.75) v2(57.4,51.56) v2(57.4,50.93) v2(57.4,48.51) v2(57.66,55.12) v2(57.66,54.48) v2(57.91,49.15) v2(57.91,46.99) v2(58.17,50.17) v2(58.42,48.51) v2(58.55,45.72) v2(58.93,49.15) v2(59.05,50.17) v2(59.18,46.99) v2(59.69,45.72) v2(60.07,50.17) v2(60.45,46.99) v2(62.87,46.99) v2(63.5,45.72) v2(64.14,51.82) v2(64.14,46.99) v2(64.64,51.31) v2(64.77,45.72) v2(64.9,50.23) v2(65.15,51.82) v2(65.41,46.99) v2(65.53,51.31) v2(65.91,51.82) v2(66.04,45.72) v2(66.29,51.31) v2(66.67,46.99) v2(66.67,29.85) v2(66.67,28.58) v2(66.67,27.31) v2(66.67,26.04) v2(67.18,51.31) v2(67.31,48.26) v2(67.31,45.72) v2(67.95,88.27) v2(67.95,87) v2(67.95,85.72) v2(67.95,84.45) v2(67.95,46.99) v2(67.95,29.85) v2(67.95,28.58) v2(67.95,27.31) v2(67.95,26.04) v2(68.07,51.31) v2(68.58,48.26) v2(68.58,45.72) v2(68.83,51.31) v2(69.22,88.27) v2(69.22,87) v2(69.22,85.72) v2(69.22,84.45) v2(69.22,46.99) v2(69.22,29.85) v2(69.22,28.58) v2(69.22,27.31) v2(69.22,26.04) v2(69.85,48.26) v2(69.85,45.72) v2(70.36,50.67) v2(70.48,88.27) v2(70.48,87) v2(70.48,85.72) v2(70.48,84.45) v2(70.48,46.99) v2(70.48,29.85) v2(70.48,28.58) v2(70.48,27.31) v2(70.48,26.04) v2(70.87,50.04) v2(71.12,48.26) v2(71.12,45.72) v2(71.25,50.67) v2(71.75,88.27) v2(71.75,87) v2(71.75,85.72) v2(71.75,84.45) v2(71.75,50.04) v2(71.75,46.99) v2(71.75,29.85) v2(71.75,28.58) v2(71.75,27.31) v2(71.75,26.04) v2(72.26,50.67) v2(72.39,48.26) v2(72.39,45.72) v2(72.77,50.04) v2(73.03,88.27) v2(73.03,87) v2(73.03,85.72) v2(73.03,84.45) v2(73.03,46.99) v2(73.03,29.85) v2(73.03,28.58) v2(73.03,27.31) v2(73.03,26.04) v2(73.66,48.26) v2(73.66,45.72) v2(73.79,50.67) v2(74.3,88.27) v2(74.3,87) v2(74.3,85.72) v2(74.3,84.45) v2(74.3,50.04) v2(74.3,46.99) v2(74.3,29.85) v2(74.3,28.58) v2(74.3,27.31) v2(74.3,26.04) v2(74.68,50.67) v2(74.93,48.26) v2(74.93,45.72) v2(75.18,50.04) v2(75.56,88.27) v2(75.56,87) v2(75.56,85.72) v2(75.56,84.45) v2(75.56,46.99) v2(75.56,29.85) v2(75.56,28.58) v2(75.56,27.31) v2(75.56,26.04) v2(75.69,50.67) v2(76.2,50.04) v2(76.2,48.26) v2(76.2,45.72) v2(76.84,88.27) v2(76.84,87) v2(76.84,85.72) v2(76.84,84.45) v2(76.84,46.99) v2(76.84,29.85) v2(76.84,28.58) v2(76.84,27.31) v2(76.84,26.04) v2(77.47,45.72) v2(78.11,88.27) v2(78.11,87) v2(78.11,85.72) v2(78.11,84.45) v2(78.11,29.85) v2(78.11,28.58) v2(78.11,27.31) v2(78.11,26.04) v2(79.38,88.27) v2(79.38,87) v2(79.38,85.72) v2(79.38,84.45) v2(79.38,50.42) v2(79.38,29.85) v2(79.38,28.58) v2(79.38,27.31) v2(79.38,26.04) v2(79.88,49.78) v2(80.01,48.26) v2(80.64,88.27) v2(80.64,87) v2(80.64,85.72) v2(80.64,84.45) v2(80.64,29.85) v2(80.64,28.58) v2(80.64,27.31) v2(80.64,26.04) v2(81.03,50.42) v2(81.28,48.26) v2(81.28,46.99) v2(81.53,49.78) v2(81.91,88.27) v2(81.91,87) v2(81.91,85.72) v2(81.91,84.45) v2(81.91,45.72) v2(81.91,29.85) v2(81.91,28.58) v2(81.91,27.31) v2(81.91,26.04) v2(82.42,49.78) v2(82.55,48.26) v2(82.55,46.99) v2(82.93,50.42) v2(83.19,88.27) v2(83.19,87) v2(83.19,85.72) v2(83.19,84.45) v2(83.19,45.72) v2(83.19,29.85) v2(83.19,28.58) v2(83.19,27.31) v2(83.19,26.04) v2(83.44,49.78) v2(83.82,48.26) v2(83.82,46.99) v2(84.45,88.27) v2(84.45,87) v2(84.45,85.72) v2(84.45,84.45) v2(84.45,50.17) v2(84.45,45.72) v2(84.45,29.85) v2(84.45,28.58) v2(84.45,27.31) v2(84.45,26.04) v2(85.09,48.13) v2(85.09,46.99) v2(85.72,88.27) v2(85.72,87) v2(85.72,85.72) v2(85.72,84.45) v2(85.72,50.17) v2(85.72,45.72) v2(85.72,29.85) v2(85.72,28.58) v2(85.72,27.31) v2(85.72,26.04) v2(86.36,51.44) v2(86.36,48.9) v2(86.36,46.99) v2(87,88.27) v2(87,87) v2(87,85.72) v2(87,84.45) v2(87,50.17) v2(87,47.62) v2(87,29.85) v2(87,28.58) v2(87,27.31) v2(87,26.04) v2(87.63,51.44) v2(87.63,48.9) v2(87.63,46.36) v2(88.27,88.27) v2(88.27,87) v2(88.27,85.72) v2(88.27,84.45) v2(88.27,50.17) v2(88.27,47.62) v2(88.27,29.85) v2(88.27,28.58) v2(88.27,27.31) v2(88.27,26.04) v2(88.9,51.44) v2(88.9,48.9) v2(88.9,46.36) v2(89.53,88.27) v2(89.53,87) v2(89.53,85.72) v2(89.53,84.45) v2(89.53,50.17) v2(89.53,47.62) v2(89.53,29.85) v2(89.53,28.58) v2(89.53,27.31) v2(89.53,26.04) v2(90.17,51.44) v2(90.17,48.9) v2(90.17,46.36) v2(90.81,88.27) v2(90.81,87) v2(90.81,85.72) v2(90.81,84.45) v2(90.81,50.17) v2(90.81,47.62) v2(90.81,29.85) v2(90.81,28.58) v2(90.81,27.31) v2(90.81,26.04) v2(91.44,51.44) v2(91.44,48.9) v2(91.44,46.36) v2(92.08,88.27) v2(92.08,87) v2(92.08,85.72) v2(92.08,84.45) v2(92.08,50.17) v2(92.08,47.62) v2(92.71,51.44) v2(92.71,48.9) v2(92.71,46.36) v2(93.34,50.17) v2(93.34,47.62) v2(93.98,51.44) v2(93.98,48.9) v2(93.98,46.36) v2(94.62,50.17) v2(94.62,47.62) v2(95,80.65) v2(95.25,51.44) v2(95.25,48.9) v2(95.25,46.36) v2(95.88,50.17) v2(95.88,47.62) v2(96.52,51.44) v2(96.52,48.9) v2(96.52,46.36) v2(96.9,85.09) v2(96.9,84.33) v2(96.9,82.8) v2(96.9,82.04) v2(97.16,50.17) v2(97.16,47.62) v2(97.79,51.44) v2(97.79,48.9) v2(97.79,46.36) v2(98.43,50.17) v2(98.43,47.62) v2(99.06,51.44) v2(99.06,48.9) v2(99.06,46.36) v2(99.69,50.17) v2(99.69,47.62) v2(100.33,51.44) v2(100.33,48.9) v2(100.33,46.36) v2(105.41,28.96) v2(106.3,48.26) v2(107.19,48.26) v2(108.2,48.26) v2(111.38,48.26) v2(112.27,48.26) v2(113.28,48.26)
GND_SIGNAL: length 49.4
  TOP w0.305: C15.1 63.24,57.4 62.56,56.72 v1(62.56,55.74)
  LAYER_3 w0.305: v2(61.08,69.6) 61.64,70.16 61.64,86.91 78.87,104.14 TP22.1
  BOTTOM w0.305: R4.1 v2(57.4,58.67) ; R9.1 v2(61.08,69.6)
  BOTTOM w0.508: R9.1 R6.1
VCC: length 107.6
  LAYER_3 w0.152: v1(61.76,54.94) 61.34,55.36 61.34,57.02
  LAYER_3 w0.508: 58.42,103.5 P10.3 ; 58.42,103.5 56.13,101.22 56.13,60.2 ; 58.42,103.5 TP2.1 53.23,99.58 38.28,99.58 ; 38.28,99.58 35.87,97.65 v2(18.58,97.65) ; 38.28,99.58 v2(38.28,100.12) ; 61.34,57.02 61.34,57.15 60.71,57.79 57.15,57.79 56.13,58.8 56.13,60.2 ; 56.13,60.2 v2(55.37,60.2)
  BOTTOM w0.508: C13.2 56.13,59.89 55.82,60.2 v2(55.37,60.2) ; R27.1 v2(38.28,100.12) R25.1 ; R23.1 v2(18.58,97.65)
VIN: length 41.3
  LAYER_5 w0.305: v2(56.4,52.57) 56.2,52.37 24.21,52.37 20.95,55.63 TP5.1
  BOTTOM w0.152: C17.1 47.88,53.72 v2(48.13,53.98) ; C3.1 54.99,53.85 v2(54.86,53.98) ; C2.P 16.13,56.77 ; C4.1 51.44,53.85 v2(51.31,53.98)
  vias: v1(58.56,53.34) v1(58.56,52.54) v1(59.36,53.34) v1(59.36,52.54) v1(60.16,53.34) v1(60.16,52.54) v2(13.97,58.42) v2(13.97,57.53) v2(13.97,56.77) v2(13.97,56.01) v2(13.97,55.12) v2(16,58.42) v2(16,57.53) v2(16,56.77) v2(16,56.01) v2(16,55.12) v2(31.12,59.06) v2(31.75,56.52) v2(31.75,53.98) v2(32.39,59.06) v2(32.39,57.79) v2(32.39,55.25) v2(33.02,56.52) v2(33.02,53.98) v2(33.66,59.06) v2(33.66,57.79) v2(33.66,55.25) v2(34.29,56.52) v2(34.29,53.98) v2(34.92,59.06) v2(34.92,57.79) v2(34.92,55.25) v2(35.56,56.52) v2(35.56,53.98) v2(36.2,59.06) v2(36.2,57.79) v2(36.2,55.25) v2(36.83,56.52) v2(36.83,53.98) v2(37.47,59.06) v2(37.47,57.79) v2(37.47,55.25) v2(38.1,56.52) v2(38.1,53.98) v2(38.73,59.06) v2(38.73,57.79) v2(38.73,55.25) v2(39.37,56.52) v2(39.37,53.98) v2(40.01,59.06) v2(40.01,57.79) v2(40.01,55.25) v2(40.64,56.52) v2(40.64,53.98) v2(41.28,59.06) v2(41.28,57.79) v2(41.28,55.25) v2(41.91,56.52) v2(41.91,53.98) v2(42.55,59.06) v2(42.55,57.79) v2(42.55,55.25) v2(43.18,56.52) v2(43.18,53.98) v2(43.81,59.06) v2(43.81,57.79) v2(43.81,55.25) v2(44.45,56.52) v2(44.45,53.98) v2(45.09,59.06) v2(45.09,57.79) v2(45.09,55.25) v2(45.72,56.52) v2(45.72,53.98) v2(46.36,59.06) v2(46.36,57.79) v2(46.36,55.25) v2(46.86,53.98) v2(46.99,56.52) v2(47.62,59.06) v2(47.62,57.79) v2(47.62,55.25) v2(48.26,56.52) v2(48.9,59.06) v2(48.9,57.79) v2(48.9,55.25) v2(49.4,53.98) v2(49.53,56.52) v2(50.16,59.06) v2(50.16,57.79) v2(50.16,55.25) v2(50.55,54.74) v2(50.55,53.98) v2(50.8,56.52) v2(51.31,54.74) v2(51.44,57.79) v2(51.44,55.25) v2(52.07,56.52) v2(52.2,54.74) v2(52.2,53.98) v2(52.7,55.25) v2(53.09,54.74) v2(53.09,53.98) v2(53.98,55.25) v2(55.25,54.48) v2(55.63,53.98) v2(57.28,53.21) v2(57.28,52.58)
BIAS: length 82.2
  LAYER_4 w0.152: v1(62.56,53.34) 62.56,53.42 62.98,53.84 62.98,56.76 63.25,57.02
  LAYER_4 w0.305: 63.25,57.02 63.25,59.56 62.1,60.71 62.1,68.2 62.36,68.45 62.36,71.5 60.83,73.03 60.83,90.81 69.22,99.19 69.22,102.24 P10.1
  BOTTOM w0.305: C8.1 87.76,103.64 TP4.1 85.92,106.49 69.66,106.49 67.95,104.78 P10.1
CLK: length 150.3
  LAYER_3 w0.305: P11.1 37.21,7.87 TP15.1 39.09,6.35 42.19,3.25 59.94,3.25 66.42,9.73 68.43,9.73 69.24,8.92 69.24,7.78 P3.B2
  LAYER_4 w0.152: 62.14,49.9 62.14,53.5 61.92,53.72 61.59,53.72 61.34,53.98 61.34,54.61 61.01,54.94 v1(60.96,54.94) 60.96,55.11 60.55,55.52 60.55,58.34 60.4,58.5
  LAYER_4 w0.305: 60.4,58.5 59.05,59.84 59.05,91.95 v2(68.45,101.35) ; 62.14,49.9 62.14,10.88 62.48,10.54 66.48,10.54 P3.B2
  BOTTOM w0.305: P11.1 32.45,8.06 C14.2 ; v2(68.45,101.35) 67.91,101.35 R21.2
DATA: length 140
  LAYER_3 w0.152: v1(60.96,55.74) 60.54,55.32 60.54,55.1 60.54,55.1 60.54,54.78 60.54,54.78 60.79,54.52 61.12,54.52 61.34,54.3 v2(61.34,49.4)
  LAYER_4 w0.305: v2(67.82,99.06) 59.69,90.94 59.69,60.07 60.96,58.8 v1(60.96,55.74) ; P11.3 32.13,9.91 45.47,9.91 ; 45.47,9.91 45.47,6.6 TP16.1 ; 45.47,9.91 61.34,9.91 ; 61.34,9.91 65.53,9.91 67.31,8.13 P3.B1 ; 61.34,9.91 v2(61.34,49.4)
  BOTTOM w0.305: C11.2 30.87,8.65 P11.3 ; R22.2 67.78,99.1 v2(67.82,99.06)
EN: length 96.7
  LAYER_4 w0.152: 59.44,56.2 59.52,56.12 60.54,55.1 60.54,54.02 60.8,53.76 61.12,53.76 61.54,53.34 v1(61.76,53.34)
  LAYER_4 w0.305: 59.44,56.2 59.44,58.55 58.42,59.56 58.42,92.58 48.51,102.49 48.51,103.63 44.07,108.08 35.05,108.08 31.12,104.14 TP14.1
  BOTTOM w0.305: C10.2 R23.2 20.28,100.49 S1.5 S1.2 20.62,105.08 21.59,106.05 28.58,106.05 TP14.1
PGOOD: length 64.9
  LAYER_4 w0.152: v1(60.96,53.34) 60.7,53.34 60.28,53.76 60,53.76 59.78,53.98 59.78,54.33 59.55,54.56 58.4,54.56 58.17,54.79 58.17,56.39
  LAYER_4 w0.305: 58.17,56.39 58.24,56.46 58.24,58.98 57.91,59.31 57.91,90.68 TP17.1
  BOTTOM w0.305: R25.2 R26.1 42.12,101.81 TP17.1
UNNAMED_2_ADLTM4740_I1_PGM0: length 18.9
  LAYER_4 w0.305: v1(61.76,55.74) 61.76,59.02 60.33,60.45 60.33,71.12 v2(60.71,71.5)
  BOTTOM w0.305: R6.2 59.57,71.5 v2(60.71,71.5)
UNNAMED_2_ADLTM4740_I1_PGM1: length 19.1
  LAYER_4 w0.152: v1(61.76,54.14) 61.89,54.14 62.18,54.43 62.18,56.72 62.59,57.12
  LAYER_4 w0.305: v2(61.08,70.6) 61.72,69.96 61.72,69.09 60.96,68.33 60.96,60.83 62.59,59.21 62.59,57.12
  BOTTOM w0.305: R9.2 v2(61.08,70.6)
UNNAMED_2_ADLTM4740_I1_SNSN: length 4.9
  TOP w0.152: R13.2 60.96,57.41 60.96,56.54 U1.E1
  TOP w0.305: R13.2 C15.2 62.64,57.93 62.64,57.99 62.82,58.17 62.87,58.17 63.13,58.42 R1.1
UNNAMED_2_ADLTM4740_I1_SNSP: length 4.7
  TOP w0.305: R10.1 60.98,58.55 R12.2 60.07,57.54 R13.1 60.08,56.9 v2(60.07,56.9)
  LAYER_3 w0.152: v1(60.16,54.94) 60.07,55.03 v2(60.07,56.9)
UNNAMED_2_ADLTM4740_I1_SW: length 1.3
  BOTTOM w0.305: 63.37,50.93 v1(63.36,50.94)
  BOTTOM w0.508: C6.1 63.37,50.93
UNNAMED_2_CAP_I18_N1: length 1.1
  TOP w0.305: C16.1 R10.2
UNNAMED_2_CAP_I18_N2: length 4.5
  TOP w0.305: R12.1 60.83,59.56 C16.2 61.21,59.94 61.21,60.45 61.42,60.66 62.91,60.66 63.13,60.44 R16.1
UNNAMED_2_CAP_I228_N2: length 1.7
  BOTTOM w0.305: R2.1 63.7,48.33 C6.2
UNNAMED_2_CNBNC5P_I173_CNTR: length 14.6
  BOTTOM w0.508: J1.1 101.09,87.76 103.31,85.54 R20.1 103.63,83.25
  BOTTOM w1.016: 103.63,78.87 103.63,83.25
UNNAMED_2_CNTP1P_I182_N1: length 20.6
  LAYER_4 w0.305: TP21.1 104.29,85.72 v2(97.47,78.91)
  BOTTOM w0.508: 99.02,78.91 99.06,78.87
  BOTTOM w0.762: 99.02,78.91 v2(97.47,78.91) R17.2
UNNAMED_6_CN3P_I255_N2: length 3.9
  BOTTOM w0.305: P10.2 66.08,103.37 R21.1 R22.1
UNNAMED_6_DIOLED_I288_N: length 3.3
  BOTTOM w0.305: Q2.3 34.67,102.62 36.2,104.14 v2(36.55,104.14)
UNNAMED_6_DIOLED_I288_P: length 2.5
  BOTTOM w0.305: v2(38.13,104.14) 38.13,102.35 R27.2
UNNAMED_6_RES_I285_N2: length 6.3
  BOTTOM w0.508: R26.2 39.46,98.68 36.45,98.68 35.61,99.52 Q2.1
UNNAMED_6_SWDPDTV5_I246_NC1: length 3.3
  BOTTOM w0.305: S1.4 S1.1
VOUT: length 102.5
  TOP w0.305: R16.2 64.49,59.82 v2(64.69,59.61)
  LAYER_3 w0.305: v2(101.22,34.93) J2.1 97.28,28.96 78.36,47.88 78.36,50.55 75.44,53.47 v2(74.8,53.47)
  LAYER_4 w0.305: TP19.1 103,58.29 103,54.23 102.36,53.59 85.34,53.59 83.82,52.07 70.1,52.07 69.09,53.09 65.02,53.09 v2(64.77,53.34) 64.77,57.66 65.41,58.29 65.41,59.18 64.97,59.61 v2(64.69,59.61)
  BOTTOM w0.305: C29.1 v2(74.8,53.47) ; C23.2 J2.1 ; J2.1 C34.2 ; J2.1 C26.2
  vias: v1(58.56,55.74) v1(58.55,55.37) v1(58.56,54.94) v1(58.93,55.75) v1(58.93,55.37) v1(58.93,54.99) v1(59.31,55.37) v1(59.36,55.74) v1(59.36,54.94) v1(63.36,55.74) v1(63.36,54.94) v1(63.36,54.14) v1(63.36,53.34) v2(58.8,56.52) v2(66.04,57.15) v2(66.42,54.36) v2(66.67,58.42) v2(67.31,57.15) v2(67.31,54.36) v2(67.56,56.13) v2(67.56,55.5) v2(67.95,59.69) v2(67.95,58.42) v2(68.07,54.36) v2(68.33,56.13) v2(68.33,55.5) v2(68.58,57.15) v2(68.96,54.36) v2(69.22,59.69) v2(69.22,58.42) v2(69.34,56.13) v2(69.34,55.5) v2(69.85,57.15) v2(70.23,53.47) v2(70.36,56.13) v2(70.36,55.5) v2(70.48,59.69) v2(70.48,58.42) v2(71.12,57.15) v2(71.25,56.13) v2(71.25,55.5) v2(71.25,53.47) v2(71.75,59.69) v2(71.75,58.42) v2(72.01,56.13) v2(72.01,55.5) v2(72.01,53.47) v2(72.39,57.15) v2(73.03,59.69) v2(73.03,58.42) v2(73.03,56.13) v2(73.03,55.5) v2(73.03,53.47) v2(73.66,57.15) v2(74.3,59.69) v2(74.3,58.42) v2(74.93,57.15) v2(74.93,56.13) v2(74.93,55.5) v2(75.56,59.69) v2(75.56,58.42) v2(75.69,56.13) v2(75.69,55.5) v2(76.2,57.15) v2(76.58,56.13) v2(76.58,55.5) v2(76.58,53.47) v2(76.84,59.69) v2(76.84,58.42) v2(77.47,57.15) v2(77.47,56.13) v2(77.47,55.5) v2(77.47,53.47) v2(78.11,59.69) v2(78.11,58.42) v2(78.36,56.13) v2(78.36,55.5) v2(78.36,53.47) v2(78.74,57.15) v2(79.25,56.13) v2(79.25,55.5) v2(79.25,53.47) v2(79.38,59.69) v2(79.38,58.42) v2(80.01,57.15) v2(80.14,56.13) v2(80.14,55.5) v2(80.64,59.69) v2(80.64,58.42) v2(81.03,56.13) v2(81.03,55.5) v2(81.15,53.47) v2(81.28,57.15) v2(81.91,59.69) v2(81.91,58.42) v2(81.91,56.13) v2(81.91,55.5) v2(81.91,53.47) v2(82.55,57.15) v2(82.68,56.13) v2(82.68,55.5) v2(82.68,53.47) v2(83.19,58.42) v2(83.82,59.69) v2(83.82,57.15) v2(84.45,58.42) v2(84.45,55.88) v2(85.09,59.69) v2(85.09,57.15) v2(85.09,54.61) v2(85.72,58.42) v2(85.72,55.88) v2(86.36,59.69) v2(86.36,57.15) v2(86.36,54.61) v2(87,58.42) v2(87,55.88) v2(87.63,59.69) v2(87.63,57.15) v2(87.63,54.61) v2(88.27,58.42) v2(88.27,55.88) v2(88.9,59.69) v2(88.9,57.15) v2(88.9,54.61) v2(89.53,58.42) v2(89.53,55.88) v2(90.17,59.69) v2(90.17,57.15) v2(90.17,54.61) v2(90.81,58.42) v2(90.81,55.88) v2(91.44,59.69) v2(91.44,57.15) v2(91.44,54.61) v2(92.08,58.42) v2(92.08,55.88) v2(92.71,59.69) v2(92.71,57.15) v2(92.71,54.61) v2(93.34,58.42) v2(93.34,55.88) v2(93.98,59.69) v2(93.98,57.15) v2(93.98,54.61) v2(94.62,58.42) v2(94.62,55.88) v2(95.25,59.69) v2(95.25,57.15) v2(95.25,54.61) v2(95.88,58.42) v2(95.88,55.88) v2(96.52,59.69) v2(96.52,57.15) v2(96.52,54.61) v2(97.16,58.42) v2(97.16,55.88) v2(97.79,59.69) v2(97.79,57.15) v2(97.79,54.61) v2(98.43,58.42) v2(98.43,55.88) v2(99.06,59.69) v2(99.06,57.15) v2(99.06,54.61) v2(99.69,58.42) v2(99.69,55.88) v2(100.33,59.69) v2(100.33,57.15) v2(100.33,54.61) v2(100.97,55.88) v2(101.6,54.61) v2(106.43,57.15) v2(107.31,57.15) v2(108.08,57.15) v2(111.63,57.15) v2(112.52,57.15) v2(113.28,57.15)

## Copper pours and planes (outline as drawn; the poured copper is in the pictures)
GND_POWER on TOP: 1.27,109.22 120.65,109.22 120.65,1.27 1.27,1.27 ; 12 cut-outs
GND_POWER on BOTTOM: 1.27,109.22 1.27,1.27 120.65,1.27 120.65,109.22 ; 2 cut-outs
GND_POWER on LAYER_2: 1.27,109.22 120.65,109.22 120.65,1.27 1.27,1.27 ; 12 cut-outs
GND_POWER on LAYER_3: 1.27,109.22 120.65,109.22 120.65,1.27 1.27,1.27 ; 10 cut-outs
GND_POWER on LAYER_4: 1.27,109.22 120.65,109.22 120.65,1.27 1.27,1.27 ; 5 cut-outs
GND_POWER on LAYER_5: 1.27,109.22 120.65,109.22 120.65,1.27 1.27,1.27 ; 11 cut-outs
GND_SIGNAL on LAYER_3: 56.64,69.98 62.87,69.98 62.87,55.5 62.45,55.5 60.96,57.06 60.96,58.04 60.71,58.29 57.28,58.29 56.64,58.93
VIN on TOP: 1.27,66.8 43.56,66.8 56.64,53.72 60.45,53.72 60.45,52.2 1.27,52.2 ; 1 cut-out
VIN on BOTTOM: 1.27,66.8 43.56,66.8 56.64,53.72 60.58,53.72 60.58,52.2 1.27,52.2 ; 1 cut-out
UNNAMED_2_ADLTM4740_I1_SW on BOTTOM: 62.99,51.18 62.99,49.28 63.88,49.28 63.88,51.18
UNNAMED_2_CAP_I228_N2 on BOTTOM: 62.99,49.02 62.99,47.75 65.66,47.75 65.66,49.02
UNNAMED_2_CNBNC5P_I173_CNTR on BOTTOM: 102.23,85.47 102.23,79.5 104.78,79.5 104.78,85.47
VOUT on TOP: 58.17,56.9 58.17,54.74 59.56,54.74 59.56,56.9
VOUT on TOP: 73.41,75.56 120.65,75.56 120.65,52.96 63.12,52.96 63.12,55.75 67.18,59.82 67.18,69.34 ; 1 cut-out
VOUT on BOTTOM: 70.61,75.56 120.65,75.56 120.65,52.96 63.12,52.96 63.12,56.39 61.34,56.39 61.34,54.74 58.29,54.74 58.29,63.25 ; 1 cut-out
VOUT on LAYER_3: 58.29,57.15 58.29,54.74 59.69,54.74 59.69,57.15
VOUT on LAYER_3: 73.28,75.44 120.65,75.44 120.65,52.96 76.58,52.96 75.56,53.98 74.3,53.98 74.3,52.96 63.12,52.96 63.12,55.75 67.18,59.82 67.18,69.34 ; 1 cut-out

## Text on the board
Ref Des/Silkscreen Bottom: GND_REG | VO_REG
Ref Des/Silkscreen Top: 3V-15V | GND | VIN | EN | PGOOD | VCC | CLK/DAT PWR | TO DC1613A | SGND | BIAS | IOUT_STEP | VOUT | IOSTEP CLK | 0.4V-5.5V | TP_CLK | TP_DATA | TP_3V3 | 15A | EVAL-LTM4740-AZ | LTM4740 | WITH PMBUS | MODULE REGULATOR
User.11: 01-081114b
User.15: LAYER 3 | LAYER 5 | LAYER 2 | LAYER 4 | IC_U1; | VIA HOLES; | PER IPC-4552 LATEST REVISION | INTERNAL LAYERS 2 OZ. COPPER. | CLADDING SPECIFICATIONS THEN THE LAYER STACKUP SHALL | TAKE PRECEDENCE. | DESIGN HAS SOLDER MASK DEFINED PADS ON U1. | U1 SOLDERMASK IS 12 MIL AND PAD SIZE IS 16 MIL. | DO NOT CHANGE PAD SIZE OR SOLDER MASK SIZE. | NOTE:IF THE LAYER STACKUP CONFLICTS WITH THE ABOVE | PLUG ALL VIA'S WITH CONDUCTIVE COPPER AND PLATE OVER. | PLANARIZE FINAL SURFACE. | ENIG (Electroless Nickel/Immersion Gold) | FABRICATION | B | 09
User.16: 09-068340a
User.45: FIGURE | SIZE | 6.0 | 10.0 | 35.0 | 40.0 | 45.0 | 50.0 | 60.0 | 100.0 | 189.0 | 187.0 | PLATED | NON-PLATED | DRILL CHART: TOP to BOTTOM | ALL UNITS ARE IN MILS | QTY | 52 | 901 | 6 | 15 | 1 | 2 | 8 | 20 | 4 | TOLERANCE/NOTES
